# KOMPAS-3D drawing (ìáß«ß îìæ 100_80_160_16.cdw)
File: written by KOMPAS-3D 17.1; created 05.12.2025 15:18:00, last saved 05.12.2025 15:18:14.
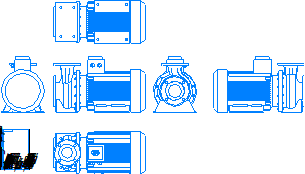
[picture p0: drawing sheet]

Sheet 1: A4, portrait

Title block, sheet 1: name: Насос МНС / 100_80_160_16; material: Сталь 10  ГОСТ 1050-88; mass: 309,93; sheets: 1; sheet format: A4

Views: Вид 1, Спереди, Проекционный вид 2, Проекционный вид 3, Проекционный вид 4, Проекционный вид 5, Проекционный вид 6
Referenced files in \\adlc.lan\data\АДЛ_ПКД\3D-модели\ADL production\Насосы ГРАНПАМП\Насосы ГРАНПАМП серии МНС\KOMPAS 3D\: Насос МНС 100-80-160_11.m3d
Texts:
  Andrey
  АДЛ
Dimensions and other numbers on the sheet: 1:1; 1; 100_80_160_16; 309,93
